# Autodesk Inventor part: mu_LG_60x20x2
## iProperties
Shininess: 64.0
Length Units: 11269
Angle Units: 11279
Time Units: 11290
Mass Units: 11283
Length Display Precision: 3
Angle Display Precision: 2
Compacted: True
Part Number: mu_LG_60x20x2
Document SubType Name: Modeling
Created: 2004-08
Designer: John Blackburn
Manufacturer: Standard
Standards Organization: Custom
Material: Lexan, Clear
Density: 0.0
Volumn: 0.0
Area: 0.0
PropertySet Name: Model Information
Control State: 0
Master: False
Checked Out: False
Author: John Blackburn
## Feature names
1. Loft1
2. Extrusion1
